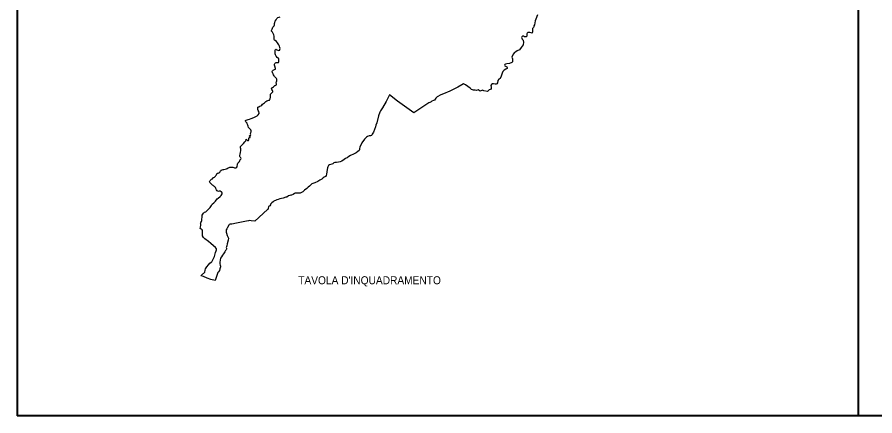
# Model space of a CAD drawing. Extents: x 652791 to 656927, y 889884 to 892405.
# Drawn here: x 652791 to 653862, y 889884 to 890382 of the extents above; entities that cross this region are included whole.
import ezdxf

# ---------------------------------------------------------------- set-up
doc = ezdxf.new("R2010")
doc.units = 0
doc.header["$LTSCALE"] = 5.6
doc.layers.add('61', color=7, linetype='Continuous', lineweight=35)

msp = doc.modelspace()

# ---------------------------------------------------------------- linework, layer by layer
at = {"layer": '61', "lineweight": 40}
for p, q in [((652791.02, 890918.43), (652791.02, 889884.41)), ((653841.02, 890918.43), (653841.02, 889884.41)), ((654894.04, 889884.41), (652791.02, 889884.41))]:
    msp.add_line(p, q, dxfattribs=at)
at = {"layer": '61', "lineweight": 25}
for points in [[(653113.41, 890376.79), (653114.61, 890378.59), (653115.15, 890380.02), (653115.75, 890380.82), (653116.71, 890381.31), (653118.29, 890381.86), (653119.59, 890382.22)], [(653440.69, 890384.99), (653438.73, 890379.27), (653438.01, 890377.42), (653437.63, 890374.74), (653437.13, 890372.31), (653436.27, 890371.03), (653436.01, 890369.75), (653435.73, 890368.95), (653434.71, 890367.91)], [(653114.55, 890333.31), (653113.63, 890334.86), (653113.21, 890336.31), (653113.23, 890337.15), (653113.23, 890338.99), (653113.27, 890340.67), (653113.47, 890341.51), (653114.01, 890341.75), (653114.65, 890341.63), (653115.39, 890341.22), (653116.41, 890340.7), (653117.97, 890340.42), (653118.87, 890340.75), (653119.21, 890341.67), (653119.27, 890342.78), (653119.05, 890344.15), (653118.73, 890345.59), (653117.97, 890347.26), (653117.07, 890348.54), (653116.11, 890349.99), (653114.73, 890351.39), (653113.41, 890352.82), (653112.33, 890353.34), (653111.93, 890353.99), (653111.99, 890354.87), (653112.05, 890356.34), (653111.83, 890358.35), (653111.43, 890360.02), (653110.59, 890361.42), (653109.75, 890363.03), (653108.73, 890364.58), (653108.77, 890365.31), (653109.47, 890366.71), (653109.99, 890368.27), (653110.43, 890369.26), (653111.89, 890371.26), (653112.25, 890372.46), (653112.17, 890374.03), (653112.59, 890375.3), (653113.41, 890376.79)], [(653434.71, 890367.91), (653434.45, 890366.39), (653434.55, 890365.07), (653434.55, 890363.71), (653434.05, 890361.75), (653432.93, 890362.31), (653431.29, 890362.71), (653429.57, 890362.75), (653428.59, 890362.62), (653427.81, 890361.99), (653427.33, 890361.19), (653427.27, 890360.39), (653427.53, 890359.3), (653427.53, 890358.31), (653426.79, 890357.46), (653425.43, 890357.27), (653424.69, 890357.51), (653423.19, 890358.02), (653421.97, 890357.98), (653421.27, 890357.51), (653420.89, 890356.55), (653421.09, 890355.67), (653421.73, 890354.62), (653422.79, 890353.39), (653423.09, 890352.74), (653423.49, 890350.66), (653422.71, 890347.35), (653420.55, 890344.23), (653418.11, 890341.1), (653415.39, 890339.78), (653413.71, 890338.83), (653411.87, 890337.9), (653410.21, 890335.62), (653408.65, 890332.11), (653409.43, 890329.86), (653409.73, 890327.75), (653409.73, 890326.34), (653408.55, 890325.31), (653406.03, 890324.07), (653402.31, 890323.51)], [(653114.85, 890298.86), (653114.61, 890299.67), (653114.61, 890300.3), (653114.85, 890301.38), (653115.27, 890302.43), (653115.47, 890303.3), (653115.19, 890304.34), (653114.67, 890305.35), (653113.49, 890306.62), (653112.81, 890307.31), (653112.21, 890307.91), (653111.83, 890308.87), (653111.23, 890309.95), (653110.59, 890311.31), (653109.73, 890312.71), (653109.37, 890313.35), (653109.31, 890313.67), (653109.31, 890314.14), (653109.81, 890315.11), (653110.71, 890315.83), (653112.47, 890316.51), (653113.49, 890317.07), (653113.69, 890317.86), (653113.29, 890319.06), (653113.01, 890319.59), (653112.63, 890320.62), (653112.27, 890321.99), (653112.57, 890323.19), (653112.99, 890324.26), (653113.81, 890325.03), (653114.61, 890325.42), (653115.47, 890325.43), (653116.75, 890325.3), (653117.25, 890325.47), (653117.71, 890326.58), (653117.87, 890327.87), (653117.77, 890329.83), (653117.33, 890330.43), (653115.67, 890331.62), (653114.55, 890333.31)], [(653402.31, 890323.51), (653400.75, 890323.42), (653399.87, 890323.03), (653399.67, 890322.07), (653400.07, 890321.23), (653402.31, 890319.71), (653402.99, 890318.95), (653402.71, 890317.74), (653401.35, 890316.87), (653399.09, 890315.75), (653397.63, 890314.14), (653396.67, 890311.91), (653395.61, 890308.23), (653394.15, 890305.5), (653392.59, 890304.55), (653391.33, 890302.66), (653390.73, 890299.99), (653389.95, 890298.67), (653388.99, 890298.3), (653387.81, 890298.47), (653385.87, 890298.78), (653384.69, 890298.58), (653383.53, 890297.91), (653382.55, 890296.59), (653382.93, 890294.71), (653383.03, 890292.82), (653382.15, 890291.75), (653380.49, 890291.19), (653379.99, 890290.91), (653378.35, 890289.22), (653373.75, 890289.95), (653372.11, 890290.74), (653369.23, 890289.39), (653366.79, 890291.19), (653364.55, 890290.34), (653362.99, 890290.74), (653361.03, 890290.63), (653358.51, 890291.75), (653356.55, 890293.19), (653353.81, 890295.35)], [(653091.61, 890267.47), (653091.61, 890268.47), (653091.73, 890269.39), (653092.23, 890269.9), (653093.13, 890270.15), (653094.21, 890270.63), (653095.31, 890271.26), (653096.47, 890272.07), (653097.59, 890273.39), (653099.83, 890275.11), (653101.55, 890276.75), (653102.91, 890277.5), (653103.87, 890277.95), (653105.23, 890278.14), (653105.99, 890278.46), (653106.67, 890279.22), (653106.93, 890279.79), (653106.99, 890280.79), (653107.27, 890281.67), (653107.43, 890282.71), (653107.37, 890283.9), (653107.35, 890285.06), (653107.57, 890285.99), (653108.03, 890286.74), (653109.45, 890287.95), (653110.21, 890288.63), (653110.41, 890289.43), (653110.07, 890290.43), (653109.19, 890291.47), (653108.83, 890292.75), (653109.09, 890293.63), (653109.69, 890294.31), (653111.23, 890295.06), (653111.93, 890295.71), (653112.63, 890296.43), (653113.41, 890296.82), (653114.25, 890297.06), (653114.73, 890297.5), (653114.85, 890298.07), (653114.85, 890298.86)], [(653353.81, 890295.35), (653350.79, 890297.26), (653348.55, 890298.58), (653346.51, 890297.54), (653341.23, 890294.71), (653338.99, 890293.27), (653331.27, 890289.59), (653323.47, 890286.19), (653320.17, 890284.87), (653315.49, 890282.3), (653313.73, 890280.9), (653312.29, 890278.31), (653310.93, 890277.79), (653308.99, 890277.19), (653307.91, 890276.22), (653306.55, 890275.55), (653304.91, 890275.07), (653303.69, 890274.35), (653286.35, 890262.43), (653266.17, 890277.11), (653255.87, 890284.79), (653251.87, 890276.79), (653247.17, 890268.95), (653244.81, 890265.07), (653244.05, 890263.42), (653242.41, 890258.66), (653239.97, 890250.03), (653239.09, 890247.26), (653238.39, 890245.15), (653237.11, 890241.67), (653235.83, 890238.46), (653234.49, 890235.91), (653233.35, 890234.43), (653232.27, 890233.91), (653230.69, 890233.67), (653228.45, 890233.1), (653227.29, 890232.31), (653224.67, 890229.63), (653221.41, 890224.91), (653218.73, 890219.83)], [(653082.15, 890232.82), (653081.71, 890233.06), (653081.39, 890233.14), (653081.13, 890233.5), (653081.13, 890233.67), (653081.39, 890234.11), (653081.85, 890234.23), (653082.47, 890234.3), (653082.93, 890234.91), (653082.61, 890236.03), (653082.73, 890238.02), (653083.37, 890238.95), (653083.31, 890240.18), (653082.81, 890241.23), (653081.71, 890242.35), (653080.63, 890243.47), (653080.05, 890244.34), (653079.29, 890245.9), (653078.91, 890247.23), (653078.39, 890248.62), (653078.07, 890249.67), (653077.57, 890250.3), (653076.53, 890251.27), (653076.27, 890252.02), (653076.35, 890252.95), (653077.05, 890253.43), (653078.19, 890253.87), (653079.55, 890254.31), (653081.19, 890254.78), (653083.17, 890255.34), (653086.49, 890256.58), (653089.11, 890257.94), (653090.91, 890258.94), (653092.05, 890260.03), (653093.07, 890261.78), (653093.07, 890262.27), (653092.77, 890264.14), (653091.99, 890265.55), (653091.67, 890266.67), (653091.61, 890267.47)], [(653065.97, 890197.43), (653066.23, 890198.62), (653066.79, 890199.86), (653067.81, 890200.79), (653068.59, 890201.95), (653069.03, 890203.19), (653069.99, 890204.51), (653070.47, 890204.9), (653070.61, 890205.58), (653070.21, 890206.27), (653069.71, 890207.26), (653069.19, 890208.07), (653069.25, 890209.35), (653069.71, 890210.98), (653069.91, 890213.14), (653070.15, 890215.5), (653070.15, 890217.47), (653070.03, 890218.9), (653069.91, 890219.83), (653070.03, 890220.7), (653070.55, 890221.26), (653071.57, 890222.23), (653073.47, 890224.18), (653075.45, 890226.22), (653076.55, 890227.7), (653076.93, 890229.07), (653077.05, 890229.47), (653077.57, 890229.27), (653078.07, 890228.47), (653078.51, 890227.91), (653079.73, 890227.99), (653080.23, 890228.66), (653080.31, 890229.59), (653080.23, 890230.58), (653080.31, 890231.34), (653080.57, 890231.39), (653081.19, 890231.63), (653081.79, 890231.87), (653082.15, 890232.26), (653082.15, 890232.82)], [(653218.73, 890219.83), (653218.41, 890218.06), (653218.47, 890216.58), (653218.05, 890215.55), (653216.57, 890214.14), (653214.27, 890212.54), (653210.95, 890210.86), (653207.31, 890209.14), (653205.09, 890208.1), (653203.23, 890206.42), (653200.95, 890205.35), (653199.27, 890204.43), (653196.27, 890202.27), (653194.23, 890201.47), (653192.39, 890200.86), (653189.71, 890200.47), (653187.79, 890200.47), (653186.51, 890200.1), (653185.41, 890198.99), (653183.77, 890198.43), (653181.03, 890197.43), (653179.81, 890196.75), (653178.79, 890195.22), (653178.45, 890194.03), (653178.09, 890191.83), (653177.27, 890185.95), (653176.83, 890184.34), (653175.99, 890183.23), (653174.59, 890182.42), (653172.99, 890181.23), (653171.39, 890179.94), (653169.09, 890178.63), (653166.41, 890176.98), (653162.71, 890175.35), (653159.13, 890173.75), (653157.87, 890172.5), (653156.19, 890171.07), (653154.53, 890169.71), (653152.55, 890167.91), (653150.01, 890165.82)], [(653031.57, 890177.1), (653032.19, 890178.07), (653032.77, 890178.95), (653033.85, 890179.55), (653034.75, 890180.11), (653035.47, 890181.31), (653035.89, 890181.71), (653036.59, 890181.9), (653037.55, 890182.27), (653038.63, 890183.38), (653039.27, 890184.35), (653040.03, 890185.35), (653040.55, 890186.23), (653040.93, 890187.1), (653041.45, 890187.27), (653042.21, 890187.27), (653042.85, 890187.71), (653043.93, 890188.58), (653044.57, 890189.34), (653045.15, 890189.95), (653045.59, 890190.7), (653046.29, 890191.19), (653047.05, 890191.43), (653048.07, 890191.67), (653049.29, 890191.91), (653050.77, 890192.18), (653052.29, 890192.47), (653053.45, 890192.99), (653054.67, 890193.83), (653055.63, 890194.27), (653056.51, 890194.59), (653057.91, 890194.71), (653059.13, 890194.71), (653060.21, 890194.59), (653061.51, 890194.34), (653062.45, 890193.83), (653064.11, 890193.91), (653065.27, 890194.71), (653065.83, 890196.07), (653065.97, 890197.43)], [(653021.97, 890132.22), (653022.23, 890134.63), (653022.81, 890136.23), (653023.89, 890137.47), (653024.97, 890138.35), (653026.77, 890139.07), (653027.91, 890140.07), (653028.99, 890141.62), (653030.91, 890142.98), (653032.19, 890144.23), (653033.01, 890145.59), (653033.61, 890147.02), (653034.69, 890148.38), (653036.73, 890150.03), (653038.83, 890152.39), (653040.93, 890155.02), (653042.09, 890156.15), (653044.41, 890158.07), (653045.67, 890159.43), (653047.09, 890161.35), (653047.21, 890162.47), (653046.63, 890163.39), (653045.73, 890164.07), (653044.53, 890164.58), (653043.45, 890164.58), (653042.61, 890164.51), (653041.71, 890164.7), (653040.75, 890165.26), (653039.99, 890166.35), (653039.03, 890167.91), (653038.59, 890169.42), (653037.57, 890170.51), (653036.79, 890171.02), (653035.89, 890171.71), (653034.87, 890172.14), (653033.85, 890173.43), (653032.65, 890174.79), (653031.51, 890175.67), (653031.37, 890176.22), (653031.57, 890177.1)], [(653150.01, 890165.82), (653147.79, 890163.91), (653144.47, 890162.23), (653143.89, 890162.3), (653141.47, 890162.23), (653139.69, 890162.11), (653138.15, 890162.3), (653137.45, 890161.79), (653135.61, 890160.75), (653133.75, 890159.83), (653132.67, 890159.71), (653131.57, 890159.46), (653129.91, 890158.78), (653127.61, 890157.35), (653126.39, 890157.35), (653123.39, 890156.23), (653121.09, 890155.5), (653119.23, 890155.35), (653116.75, 890154.5), (653115.25, 890153.83), (653113.79, 890153.02), (653112.39, 890152.59), (653111.67, 890152.15), (653110.77, 890151.3), (653109.25, 890150.03), (653107.27, 890148.55), (653107.27, 890147.63), (653106.39, 890146.31), (653105.03, 890145.47), (653104.53, 890143.11), (653104.33, 890142.23), (653103.51, 890141.75), (653087.93, 890127.46), (653083.41, 890127.9), (653081.17, 890128.02), (653079.89, 890127.83), (653077.41, 890127.35), (653073.13, 890126.54), (653064.95, 890124.87), (653059.27, 890123.75)], [(653028.17, 890056.34), (653023.83, 890058.1), (653020.81, 890059.27), (653021.29, 890060.03), (653025.55, 890063.71), (653025.75, 890066.11), (653026.39, 890068.03), (653027.91, 890070.15), (653029.89, 890072.82), (653031.81, 890074.99), (653033.15, 890076.1), (653034.05, 890076.71), (653035.19, 890078.87), (653037.31, 890083.03), (653038.19, 890086.39), (653038.77, 890088.23), (653039.55, 890090.35), (653039.97, 890091.55), (653039.85, 890092.91), (653038.83, 890094.27), (653036.41, 890096.55), (653032.83, 890099.66), (653029.77, 890101.75), (653025.21, 890105.3), (653023.57, 890107.1), (653022.47, 890109.02), (653022.41, 890111.99), (653022.55, 890115.46), (653022.03, 890116.43), (653020.69, 890117.19), (653019.73, 890118.11), (653019.87, 890119.99), (653020.25, 890122.47), (653020.31, 890123.95), (653020.17, 890124.95), (653020.37, 890125.51), (653021.13, 890126.94), (653021.53, 890128.23), (653021.65, 890129.98), (653021.97, 890132.22)], [(653059.27, 890123.75), (653056.91, 890123.58), (653055.75, 890123.19), (653055.39, 890122.15), (653053.77, 890119.3), (653052.95, 890117.63), (653052.05, 890116.31), (653052.11, 890113.71), (653052.63, 890112.18), (653053.47, 890109.55), (653054.35, 890106.87), (653054.79, 890105.95), (653054.35, 890103.78), (653053.39, 890098.99), (653052.87, 890096.47), (653052.37, 890095.42), (653052.11, 890094.67), (653052.45, 890093.79), (653052.63, 890093.18), (653052.33, 890092.19), (653051.85, 890091.47), (653051.31, 890090.59), (653050.23, 890088.95), (653048.77, 890086.63), (653047.35, 890084.7), (653046.05, 890082.67), (653044.95, 890081.19), (653044.49, 890078.59), (653044.17, 890076.07), (653043.91, 890074.15), (653044.41, 890072.42), (653044.81, 890071.15), (653044.75, 890070.22), (653044.13, 890067.95), (653043.53, 890065.86), (653042.47, 890064.06), (653041.79, 890063.18), (653038.09, 890053.15), (653033.05, 890054.71), (653028.17, 890056.34)]]:
    msp.add_lwpolyline(points, dxfattribs=at)

# ---------------------------------------------------------------- texts
at = {"layer": '61', "width": 0.95}
msp.add_text("TAVOLA D'INQUADRAMENTO", height=10, dxfattribs=at).set_placement((653142, 890048.59))

doc.saveas('drawing.dxf')
